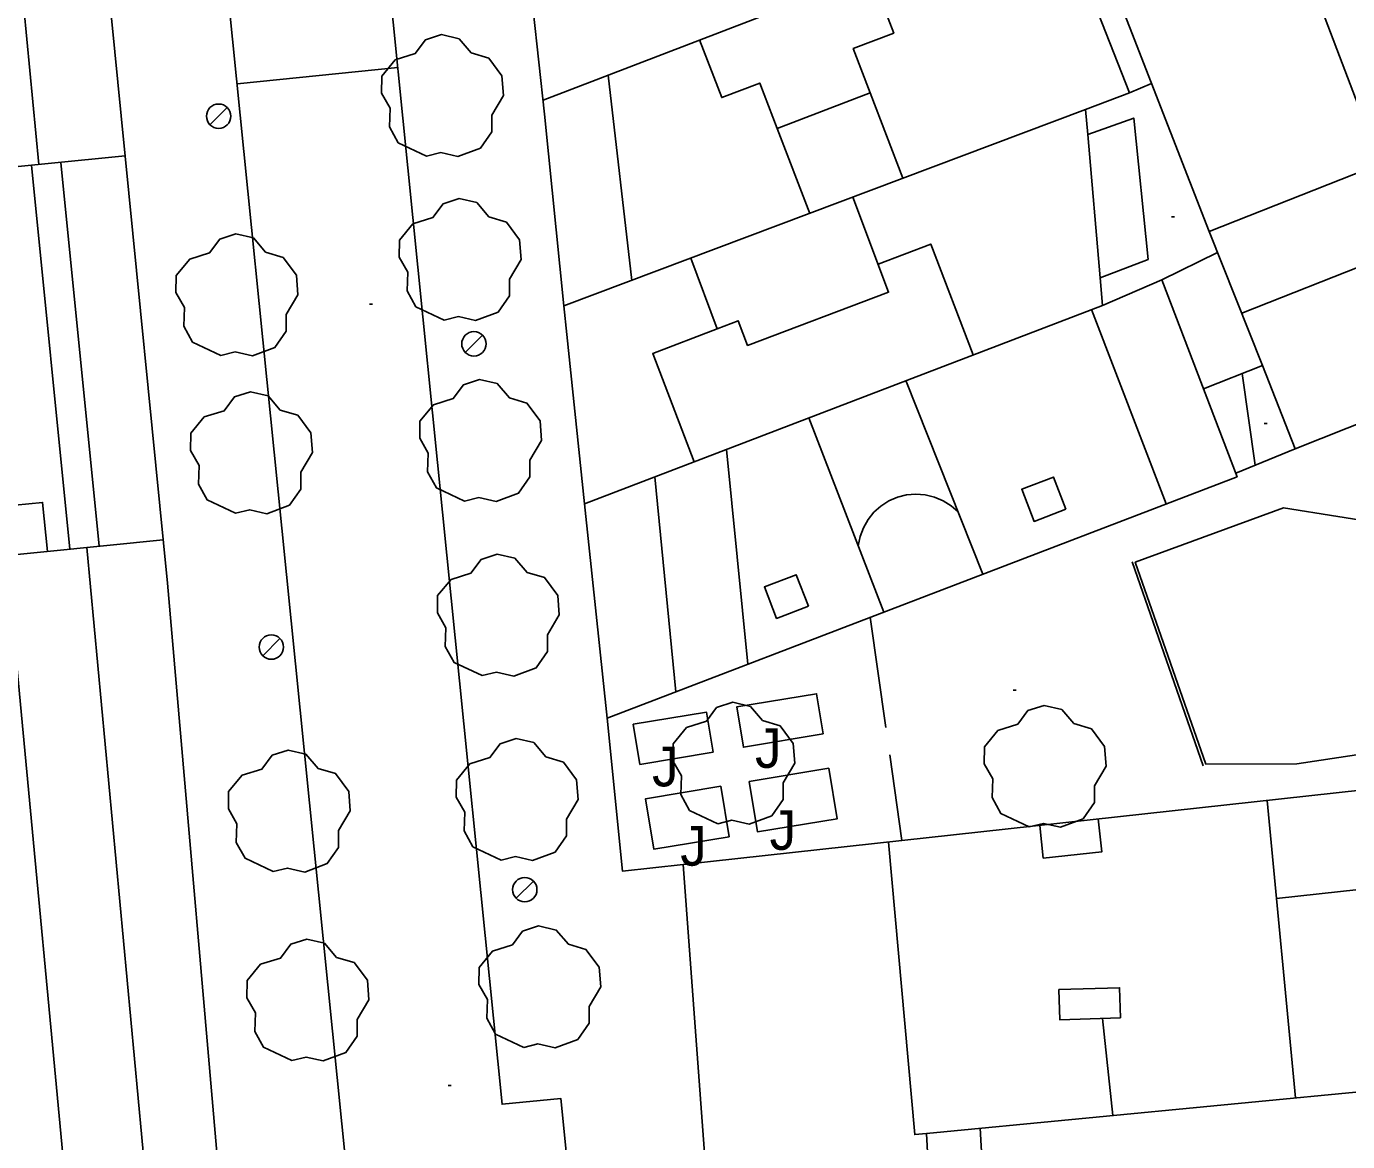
# Model space of a CAD drawing. Extents: x 431390 to 432653, y 4586754 to 4589600.
# Drawn here: x 431849.57 to 431892.94, y 4586938.41 to 4586975.01 of the extents above; entities that cross this region are included whole.
import ezdxf

# ---------------------------------------------------------------- set-up
doc = ezdxf.new("R2010")
doc.units = 0
for name, color, linetype in [('COM_17LS_LN', 7, 'Continuous'), ('COM_51_LN', 7, 'Continuous'), ('CON_01_LN', 7, 'Continuous'), ('CON_01FI_LN', 7, 'Continuous'), ('CON_03_LN', 7, 'Continuous'), ('CON_04_LN', 7, 'Continuous'), ('CON_07_LN', 7, 'Continuous'), ('CON_14LS_LN', 7, 'Continuous'), ('CON_16_LN', 7, 'Continuous'), ('CON_29_LN', 7, 'Continuous'), ('ENE_06_PT', 7, 'Continuous'), ('ORO_03_PT', 7, 'Continuous'), ('TOP_15JA_TX', 7, 'Continuous'), ('VEG_03_PT', 7, 'Continuous'), ('VEG_04_LN', 7, 'Continuous'), ('VEG_06_LN', 7, 'Continuous')]:
    doc.layers.add(name, color=color, linetype=linetype)

msp = doc.modelspace()

# ---------------------------------------------------------------- linework, layer by layer
at = {"layer": 'COM_17LS_LN'}
for points in [[(431853.209, 4587026.07), (431851.172, 4587025.865), (431854.479, 4586993.032), (431857.953, 4586958.536), (431861.124, 4586927.05), (431865.053, 4586888.028), (431868.58, 4586853.01), (431870.706, 4586853.224), (431871.5, 4586845.327)], [(431978.482, 4586940.712), (431979.21, 4586936.465), (431977.301, 4586936.133), (431968.138, 4586934.539), (431952.481, 4586931.815), (431928.554, 4586927.652), (431912.203, 4586924.807), (431895.247, 4586921.857), (431873.934, 4586918.149), (431867.46, 4586917.026), (431866.397, 4586927.581), (431865.787, 4586933.635), (431867.716, 4586933.829), (431867.112, 4586939.828), (431865.183, 4586939.634), (431863.226, 4586959.067), (431861.278, 4586978.415)], [(431896.187, 4586958.356), (431890.83, 4586959.21), (431885.97, 4586957.42), (431888.29, 4586950.8), (431891.27, 4586950.81), (431893.23, 4586951.1), (431897.868, 4586954.347)]]:
    msp.add_lwpolyline(points, dxfattribs=at)
at = {"layer": 'COM_51_LN'}
msp.add_lwpolyline([(431861.757, 4586973.653), (431856.484, 4586973.122)], dxfattribs=at)
at = {"layer": 'CON_01_LN'}
for points in [[(431916.08, 4586998.47), (431865.83, 4586978.96), (431866.58, 4586972.13)], [(431851.723, 4586981.696), (431852.679, 4586972.071)], [(431866.58, 4586972.13), (431867.209, 4586965.831)], [(431854.203, 4586956.737), (431852.679, 4586972.071)], [(431867.209, 4586965.831), (431867.308, 4586964.892), (431867.704, 4586961.121), (431867.891, 4586959.342)], [(431867.891, 4586959.342), (431868.63, 4586952.31)], [(431854.203, 4586956.737), (431856.092, 4586934.904)], [(431872.028, 4586935.375), (431871.13, 4586947.5)]]:
    msp.add_lwpolyline(points, dxfattribs=at)
at = {"layer": 'CON_01FI_LN'}
for points in [[(431897.07, 4586977.66), (431892.03, 4586975.73), (431894.02, 4586970.5), (431888.39, 4586968.28), (431883.87, 4586979.89), (431883.01, 4586979.56), (431883.24, 4586979.002), (431883.34, 4586979.04), (431885.78, 4586972.83), (431884.34, 4586972.28), (431884.41, 4586971.458), (431885.92, 4586972), (431886.391, 4586967.362), (431884.812, 4586966.757), (431884.89, 4586965.85), (431886.84, 4586966.69), (431889.31, 4586960.23), (431868.63, 4586952.31)], [(431871.13, 4586947.5), (431902.33, 4586950.93), (431904.113, 4586941.087), (431879.12, 4586938.68), (431879.27, 4586935.82), (431872.028, 4586935.375)]]:
    msp.add_lwpolyline(points, dxfattribs=at)
at = {"layer": 'CON_03_LN'}
for points in [[(431866.529, 4586972.59), (431883.24, 4586979.002)], [(431884.34, 4586972.28), (431867.209, 4586965.831)], [(431852.81, 4586970.754), (431826.872, 4586968.172)], [(431884.89, 4586965.85), (431867.891, 4586959.342)], [(431825.8, 4586958.75), (431832.476, 4586957.35), (431836.86, 4586956.43), (431854.062, 4586958.16)]]:
    msp.add_lwpolyline(points, dxfattribs=at)
at = {"layer": 'CON_04_LN'}
for points in [[(431848.791, 4586982.824), (431849.981, 4586970.472)], [(431877.299, 4586976.722), (431878.041, 4586974.789), (431876.711, 4586974.279), (431877.267, 4586972.831), (431874.215, 4586971.66), (431873.644, 4586973.148), (431872.396, 4586972.669), (431871.669, 4586974.562)], [(431869.444, 4586966.672), (431868.668, 4586973.411)], [(431877.267, 4586972.831), (431878.344, 4586970.023)], [(431874.215, 4586971.66), (431875.285, 4586968.871)], [(431884.812, 4586966.757), (431884.41, 4586971.458)], [(431849.738, 4586970.448), (431850.992, 4586957.851)], [(431850.704, 4586970.544), (431851.957, 4586957.948)], [(431871.377, 4586967.4), (431872.248, 4586965.086), (431872.937, 4586965.345), (431873.24, 4586964.54), (431877.87, 4586966.283), (431876.696, 4586969.402)], [(431880.646, 4586964.225), (431879.253, 4586967.864), (431877.524, 4586967.202)], [(431886.988, 4586959.341), (431884.531, 4586965.713)], [(431871.491, 4586960.72), (431870.13, 4586964.275), (431872.248, 4586965.086)], [(431880.964, 4586957.034), (431878.441, 4586963.381)], [(431877.715, 4586955.789), (431875.252, 4586962.16)], [(431872.552, 4586961.126), (431873.253, 4586954.08)], [(431870.199, 4586960.226), (431870.885, 4586953.174)], [(431883.69, 4586959.159), (431883.284, 4586960.218), (431882.242, 4586959.819), (431882.647, 4586958.76), (431883.69, 4586959.159)], [(431880.154, 4586959.072), (431879.921, 4586959.276), (431879.66, 4586959.44), (431879.376, 4586959.559), (431879.077, 4586959.631), (431878.769, 4586959.655), (431878.462, 4586959.629), (431878.163, 4586959.554), (431877.88, 4586959.432), (431877.621, 4586959.266), (431877.391, 4586959.061), (431877.197, 4586958.822), (431877.043, 4586958.554), (431876.935, 4586958.266), (431876.874, 4586957.964)], [(431850.263, 4586957.778), (431850.101, 4586959.387), (431848.294, 4586959.205), (431848.456, 4586957.596)], [(431853.962, 4586932.091), (431851.55, 4586957.907)], [(431848.912, 4586957.642), (431851.315, 4586932.152)], [(431875.239, 4586955.977), (431874.842, 4586957.013), (431873.797, 4586956.613), (431874.194, 4586955.577), (431875.239, 4586955.977)], [(431890.303, 4586949.608), (431891.23, 4586939.846)], [(431884.756, 4586948.998), (431884.874, 4586947.924), (431882.949, 4586947.712), (431882.831, 4586948.786)], [(431879.12, 4586938.68), (431878.728, 4586938.642), (431877.873, 4586948.241)], [(431890.609, 4586946.385), (431902.91, 4586947.728)], [(431885.484, 4586942.471), (431883.49, 4586942.41), (431883.46, 4586943.4), (431885.454, 4586943.461), (431885.484, 4586942.471)]]:
    msp.add_lwpolyline(points, dxfattribs=at)
at = {"layer": 'CON_07_LN'}
for points in [[(431890.148, 4586963.873), (431888.39, 4586968.28)], [(431886.84, 4586966.69), (431888.669, 4586967.582)], [(431889.462, 4586965.593), (431893.79, 4586967.3), (431895.48, 4586962.84), (431891.22, 4586961.14), (431890.148, 4586963.873)], [(431890.148, 4586963.873), (431888.207, 4586963.116)], [(431889.482, 4586963.613), (431889.909, 4586960.604)], [(431879.227, 4586936.639), (431880.994, 4586936.732), (431880.882, 4586938.85)]]:
    msp.add_lwpolyline(points, dxfattribs=at)
at = {"layer": 'CON_14LS_LN'}
msp.add_lwpolyline([(431891.22, 4586961.14), (431889.267, 4586960.341)], dxfattribs=at)
at = {"layer": 'CON_16_LN'}
for points in [[(431885.78, 4586972.83), (431886.501, 4586973.132)], [(431871.13, 4586947.5), (431869.14, 4586947.28), (431868.63, 4586952.31)]]:
    msp.add_lwpolyline(points, dxfattribs=at)
at = {"layer": 'CON_29_LN'}
msp.add_lwpolyline([(431885.227, 4586939.268), (431884.893, 4586942.453)], dxfattribs=at)
at = {"layer": 'ENE_06_PT'}
for p, q in [((431856.162, 4586972.342), (431855.596, 4586971.776)), ((431864.542, 4586964.872), (431863.976, 4586964.306)), ((431857.892, 4586954.922), (431857.326, 4586954.356)), ((431866.212, 4586946.962), (431865.646, 4586946.396))]:
    msp.add_line(p, q, dxfattribs=at)
for centre in [(431855.879, 4586972.059), (431864.259, 4586964.589), (431857.609, 4586954.639), (431865.929, 4586946.679)]:
    msp.add_circle(centre, 0.4, dxfattribs=at)
at = {"layer": 'ORO_03_PT'}
for p, q in [((431887.16, 4586968.76), (431887.26, 4586968.76)), ((431860.83, 4586965.894), (431860.93, 4586965.894)), ((431890.2, 4586961.98), (431890.3, 4586961.98)), ((431881.96, 4586953.22), (431882.06, 4586953.22)), ((431863.412, 4586940.256), (431863.512, 4586940.256))]:
    msp.add_line(p, q, dxfattribs=at)
at = {"layer": 'VEG_03_PT'}
for points in [[(431862.704, 4586970.751), (431861.777, 4586971.186), (431861.489, 4586971.707), (431861.512, 4586972.321), (431861.23, 4586972.813), (431861.238, 4586973.376), (431861.679, 4586973.911), (431862.332, 4586974.115), (431862.667, 4586974.566), (431863.193, 4586974.736), (431863.773, 4586974.603), (431864.173, 4586974.137), (431864.747, 4586973.967), (431865.181, 4586973.384), (431865.23, 4586972.742), (431864.847, 4586972.095), (431864.847, 4586971.545), (431864.475, 4586971.011), (431863.736, 4586970.736), (431863.171, 4586970.864), (431862.704, 4586970.751)], [(431863.284, 4586965.371), (431862.357, 4586965.806), (431862.069, 4586966.327), (431862.092, 4586966.941), (431861.81, 4586967.433), (431861.818, 4586967.996), (431862.259, 4586968.531), (431862.912, 4586968.735), (431863.247, 4586969.186), (431863.773, 4586969.356), (431864.353, 4586969.223), (431864.753, 4586968.757), (431865.327, 4586968.587), (431865.761, 4586968.004), (431865.81, 4586967.362), (431865.427, 4586966.715), (431865.427, 4586966.165), (431865.055, 4586965.631), (431864.316, 4586965.356), (431863.751, 4586965.484), (431863.284, 4586965.371)], [(431855.954, 4586964.211), (431855.027, 4586964.646), (431854.739, 4586965.167), (431854.762, 4586965.781), (431854.48, 4586966.273), (431854.488, 4586966.836), (431854.929, 4586967.371), (431855.582, 4586967.575), (431855.917, 4586968.026), (431856.443, 4586968.196), (431857.023, 4586968.063), (431857.423, 4586967.597), (431857.997, 4586967.427), (431858.431, 4586966.844), (431858.48, 4586966.202), (431858.097, 4586965.555), (431858.097, 4586965.005), (431857.725, 4586964.471), (431856.986, 4586964.196), (431856.421, 4586964.324), (431855.954, 4586964.211)], [(431856.434, 4586959.031), (431855.507, 4586959.466), (431855.219, 4586959.987), (431855.242, 4586960.601), (431854.96, 4586961.093), (431854.968, 4586961.656), (431855.409, 4586962.191), (431856.062, 4586962.395), (431856.397, 4586962.846), (431856.923, 4586963.016), (431857.503, 4586962.883), (431857.903, 4586962.417), (431858.477, 4586962.247), (431858.911, 4586961.664), (431858.96, 4586961.022), (431858.577, 4586960.375), (431858.577, 4586959.825), (431858.205, 4586959.291), (431857.466, 4586959.016), (431856.901, 4586959.144), (431856.434, 4586959.031)], [(431863.954, 4586959.431), (431863.027, 4586959.866), (431862.739, 4586960.387), (431862.762, 4586961.001), (431862.48, 4586961.493), (431862.488, 4586962.056), (431862.929, 4586962.591), (431863.582, 4586962.795), (431863.917, 4586963.246), (431864.443, 4586963.416), (431865.023, 4586963.283), (431865.423, 4586962.817), (431865.997, 4586962.647), (431866.431, 4586962.064), (431866.48, 4586961.422), (431866.097, 4586960.775), (431866.097, 4586960.225), (431865.725, 4586959.691), (431864.986, 4586959.416), (431864.421, 4586959.544), (431863.954, 4586959.431)], [(431864.534, 4586953.701), (431863.607, 4586954.136), (431863.319, 4586954.657), (431863.342, 4586955.271), (431863.06, 4586955.763), (431863.068, 4586956.326), (431863.509, 4586956.861), (431864.162, 4586957.065), (431864.497, 4586957.516), (431865.023, 4586957.686), (431865.603, 4586957.553), (431866.003, 4586957.087), (431866.577, 4586956.917), (431867.011, 4586956.334), (431867.06, 4586955.692), (431866.677, 4586955.045), (431866.677, 4586954.495), (431866.305, 4586953.961), (431865.566, 4586953.686), (431865.001, 4586953.814), (431864.534, 4586953.701)], [(431872.264, 4586948.841), (431871.337, 4586949.276), (431871.049, 4586949.797), (431871.072, 4586950.411), (431870.79, 4586950.903), (431870.798, 4586951.466), (431871.239, 4586952.001), (431871.892, 4586952.205), (431872.227, 4586952.656), (431872.753, 4586952.826), (431873.333, 4586952.693), (431873.733, 4586952.227), (431874.307, 4586952.057), (431874.741, 4586951.474), (431874.79, 4586950.832), (431874.407, 4586950.185), (431874.407, 4586949.635), (431874.035, 4586949.101), (431873.296, 4586948.826), (431872.731, 4586948.954), (431872.264, 4586948.841)], [(431882.484, 4586948.741), (431881.557, 4586949.176), (431881.269, 4586949.697), (431881.292, 4586950.311), (431881.01, 4586950.803), (431881.018, 4586951.366), (431881.459, 4586951.901), (431882.112, 4586952.105), (431882.447, 4586952.556), (431882.973, 4586952.726), (431883.553, 4586952.593), (431883.953, 4586952.127), (431884.527, 4586951.957), (431884.961, 4586951.374), (431885.01, 4586950.732), (431884.627, 4586950.085), (431884.627, 4586949.535), (431884.255, 4586949.001), (431883.516, 4586948.726), (431882.951, 4586948.854), (431882.484, 4586948.741)], [(431865.154, 4586947.651), (431864.227, 4586948.086), (431863.939, 4586948.607), (431863.962, 4586949.221), (431863.68, 4586949.713), (431863.688, 4586950.276), (431864.129, 4586950.811), (431864.782, 4586951.015), (431865.117, 4586951.466), (431865.643, 4586951.636), (431866.223, 4586951.503), (431866.623, 4586951.037), (431867.197, 4586950.867), (431867.631, 4586950.284), (431867.68, 4586949.642), (431867.297, 4586948.995), (431867.297, 4586948.445), (431866.925, 4586947.911), (431866.186, 4586947.636), (431865.621, 4586947.764), (431865.154, 4586947.651)], [(431857.674, 4586947.271), (431856.747, 4586947.706), (431856.459, 4586948.227), (431856.482, 4586948.841), (431856.2, 4586949.333), (431856.208, 4586949.896), (431856.649, 4586950.431), (431857.302, 4586950.635), (431857.637, 4586951.086), (431858.163, 4586951.256), (431858.743, 4586951.123), (431859.143, 4586950.657), (431859.717, 4586950.487), (431860.151, 4586949.904), (431860.2, 4586949.262), (431859.817, 4586948.615), (431859.817, 4586948.065), (431859.445, 4586947.531), (431858.706, 4586947.256), (431858.141, 4586947.384), (431857.674, 4586947.271)], [(431865.894, 4586941.501), (431864.967, 4586941.936), (431864.679, 4586942.457), (431864.702, 4586943.071), (431864.42, 4586943.563), (431864.428, 4586944.126), (431864.869, 4586944.661), (431865.522, 4586944.865), (431865.857, 4586945.316), (431866.383, 4586945.486), (431866.963, 4586945.353), (431867.363, 4586944.887), (431867.937, 4586944.717), (431868.371, 4586944.134), (431868.42, 4586943.492), (431868.037, 4586942.845), (431868.037, 4586942.295), (431867.665, 4586941.761), (431866.926, 4586941.486), (431866.361, 4586941.614), (431865.894, 4586941.501)], [(431858.284, 4586941.071), (431857.357, 4586941.506), (431857.069, 4586942.027), (431857.092, 4586942.641), (431856.81, 4586943.133), (431856.818, 4586943.696), (431857.259, 4586944.231), (431857.912, 4586944.435), (431858.247, 4586944.886), (431858.773, 4586945.056), (431859.353, 4586944.923), (431859.753, 4586944.457), (431860.327, 4586944.287), (431860.761, 4586943.704), (431860.81, 4586943.062), (431860.427, 4586942.415), (431860.427, 4586941.865), (431860.055, 4586941.331), (431859.316, 4586941.056), (431858.751, 4586941.184), (431858.284, 4586941.071)]]:
    msp.add_lwpolyline(points, dxfattribs=at)
at = {"layer": 'VEG_04_LN'}
for points in [[(431885.87, 4586957.44), (431888.2, 4586950.74)], [(431877.265, 4586955.617), (431877.779, 4586951.997)], [(431877.907, 4586951.1), (431878.306, 4586948.289)]]:
    msp.add_lwpolyline(points, dxfattribs=at)
at = {"layer": 'VEG_06_LN'}
for points in [[(431875.726, 4586951.787), (431875.507, 4586953.107), (431872.889, 4586952.672), (431873.108, 4586951.352), (431875.726, 4586951.787)], [(431872.11, 4586951.186), (431869.71, 4586950.788), (431869.491, 4586952.108), (431871.891, 4586952.506), (431872.11, 4586951.186)], [(431875.913, 4586950.662), (431873.295, 4586950.227), (431873.57, 4586948.571), (431876.188, 4586949.006), (431875.913, 4586950.662)], [(431872.635, 4586948.416), (431870.167, 4586948.006), (431869.892, 4586949.663), (431872.36, 4586950.073), (431872.635, 4586948.416)]]:
    msp.add_lwpolyline(points, dxfattribs=at)

# ---------------------------------------------------------------- texts
at = {"layer": 'TOP_15JA_TX'}
for p in [(431873.486, 4586950.676), (431870.108, 4586950.067), (431873.966, 4586947.986), (431871.033, 4586947.465)]:
    msp.add_text('J', height=1.3, dxfattribs=at).set_placement(p)

doc.saveas('drawing.dxf')
